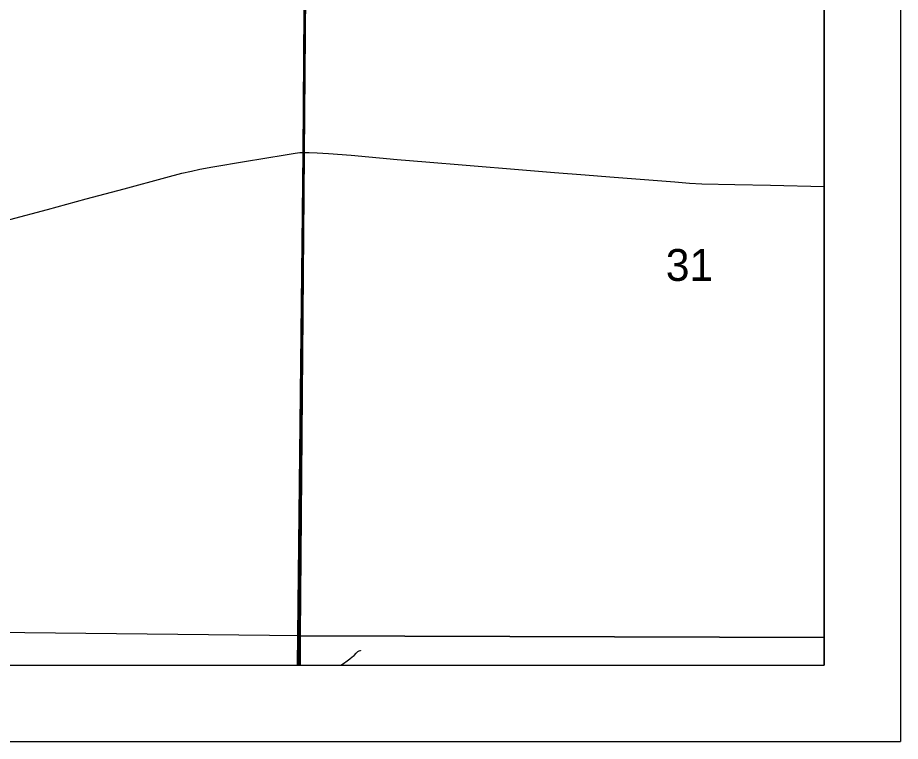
# Model space of a CAD drawing. Extents: x -17 to 88, y -5 to 22.
# Drawn here: x 8.342 to 9.5, y 14 to 14.95 of the extents above; entities that cross this region are included whole.
import ezdxf

# ---------------------------------------------------------------- set-up
doc = ezdxf.new("R2010")
doc.units = 0
for name, color, linetype in [('GM_X_County_Road', 7, 'Continuous'), ('GM_X_Minor_River', 7, 'Continuous'), ('GM_X_Section', 7, 'Continuous'), ('GM_X_Section_Text', 7, 'Continuous'), ('GM_X_State_Route', 7, 'Continuous'), ('GM_X_Township', 7, 'Continuous'), ('SH_Data', 7, 'Continuous')]:
    doc.layers.add(name, color=color, linetype=linetype)

msp = doc.modelspace()

# ---------------------------------------------------------------- linework, layer by layer
at = {"layer": 'GM_X_County_Road'}
for points in [[(8.7176, 14.773), (8.7177, 14.8061), (8.7183, 14.8496), (8.7187, 14.8931), (8.7192, 14.977), (8.7197, 15.0627), (8.7201, 15.1205), (8.7207, 15.1852), (8.7212, 15.2119), (8.7214, 15.2548), (8.7218, 15.353), (8.7224, 15.4157), (8.7227, 15.499), (8.7231, 15.5295), (8.7234, 15.5636), (8.7241, 15.6302), (8.7248, 15.7215), (8.7254, 15.7905), (8.7264, 15.8663), (8.7263, 15.8912), (8.7263, 15.892)], [(8.711, 14.1), (8.7116, 14.1803), (8.7123, 14.2449), (8.7129, 14.3102), (8.714, 14.4258), (8.715, 14.5277), (8.7161, 14.6091), (8.7174, 14.6973), (8.7174, 14.7185), (8.7175, 14.7396), (8.7176, 14.7589), (8.7176, 14.773)]]:
    msp.add_lwpolyline(points, dxfattribs=at)
at = {"layer": 'GM_X_Minor_River'}
msp.add_lwpolyline([(8.7659, 14.1), (8.7693, 14.1023), (8.7739, 14.1057), (8.7776, 14.1083), (8.7807, 14.111), (8.7833, 14.1125), (8.786, 14.1156), (8.7879, 14.1178), (8.7898, 14.119), (8.7917, 14.1194), (8.7917, 14.1197), (8.7917, 14.1194)], dxfattribs=at)
at = {"layer": 'GM_X_Section'}
for p, q in [((9.4, 14.1363), (9.4, 15.1337)), ((7.708, 14.1), (8.7123, 14.1))]:
    msp.add_line(p, q, dxfattribs=at)
msp.add_lwpolyline([(7.7144, 15.1522), (8.7205, 15.1393), (8.7126, 14.1384), (7.7079, 14.1494)], close=True, dxfattribs=at)
for points in [[(9.4, 15.1337), (8.7205, 15.1393), (8.7126, 14.1384), (9.4, 14.1363)], [(8.7123, 14.1), (8.7126, 14.1384), (7.7079, 14.1494), (7.708, 14.1)], [(9.4, 14.1363), (8.7126, 14.1384), (8.7123, 14.1)], [(8.7123, 14.1), (9.4, 14.1), (9.4, 14.1363)]]:
    msp.add_lwpolyline(points, dxfattribs=at)
at = {"layer": 'GM_X_State_Route'}
msp.add_lwpolyline([(8.3314, 14.685), (8.3807, 14.6981), (8.4317, 14.7119), (8.4815, 14.7252), (8.5361, 14.7401), (8.5571, 14.7456), (8.5698, 14.7485), (8.5807, 14.7508), (8.5978, 14.754), (8.6395, 14.7611), (8.6928, 14.7699), (8.7057, 14.7718), (8.7121, 14.7727), (8.7149, 14.7729), (8.7176, 14.773), (8.7204, 14.773), (8.7243, 14.7729), (8.7347, 14.7725), (8.7495, 14.7715), (8.7792, 14.7691), (8.8399, 14.7636), (8.8771, 14.7605), (8.9303, 14.7562), (9.004, 14.75), (9.0461, 14.7465), (9.0864, 14.7434), (9.1186, 14.7409), (9.2041, 14.7341), (9.2234, 14.7327), (9.2395, 14.7319), (9.283, 14.7308), (9.3296, 14.7299), (9.4, 14.728)], dxfattribs=at)
at = {"layer": 'GM_X_Township'}
msp.add_line((2.605, 14.1), (8.709, 14.1), dxfattribs=at)
for points in [[(8.709, 14.1), (9.4, 14.1), (9.4, 20.1669)], [(9.4, 20.1669), (8.7281, 20.1646), (8.7274, 19.89), (8.7348, 19.4138), (8.7331, 19.1436), (8.7241, 18.1383), (8.7317, 17.1395), (8.7273, 16.2993), (8.7261, 16.1499), (8.7243, 15.8906), (8.7164, 14.7728), (8.709, 14.1)], [(8.709, 14.1), (8.7164, 14.7728), (8.7243, 15.8906), (8.7261, 16.1499), (8.7273, 16.2993), (8.7317, 17.1395), (8.7241, 18.1383), (8.7331, 19.1436), (8.236, 19.1446), (7.7361, 19.149), (7.2261, 19.1535), (6.9691, 19.1558), (6.2534, 19.1527), (5.7225, 19.1491), (5.7215, 18.6472), (5.7149, 18.1469), (5.0464, 18.1513)]]:
    msp.add_lwpolyline(points, dxfattribs=at)
at = {"layer": 'SH_Data'}
for p, q in [((9.5, 21), (9.5, 14)), ((9.4, 20.9), (9.4, 14.1)), ((2.6, 14.1), (9.4, 14.1)), ((2.5, 14), (9.5, 14))]:
    msp.add_line(p, q, dxfattribs=at)

# ---------------------------------------------------------------- texts
at = {"layer": 'GM_X_Section_Text'}
msp.add_text('31', height=0.04186, rotation=0, dxfattribs=at).set_placement((9.1922, 14.6043))

doc.saveas('drawing.dxf')
